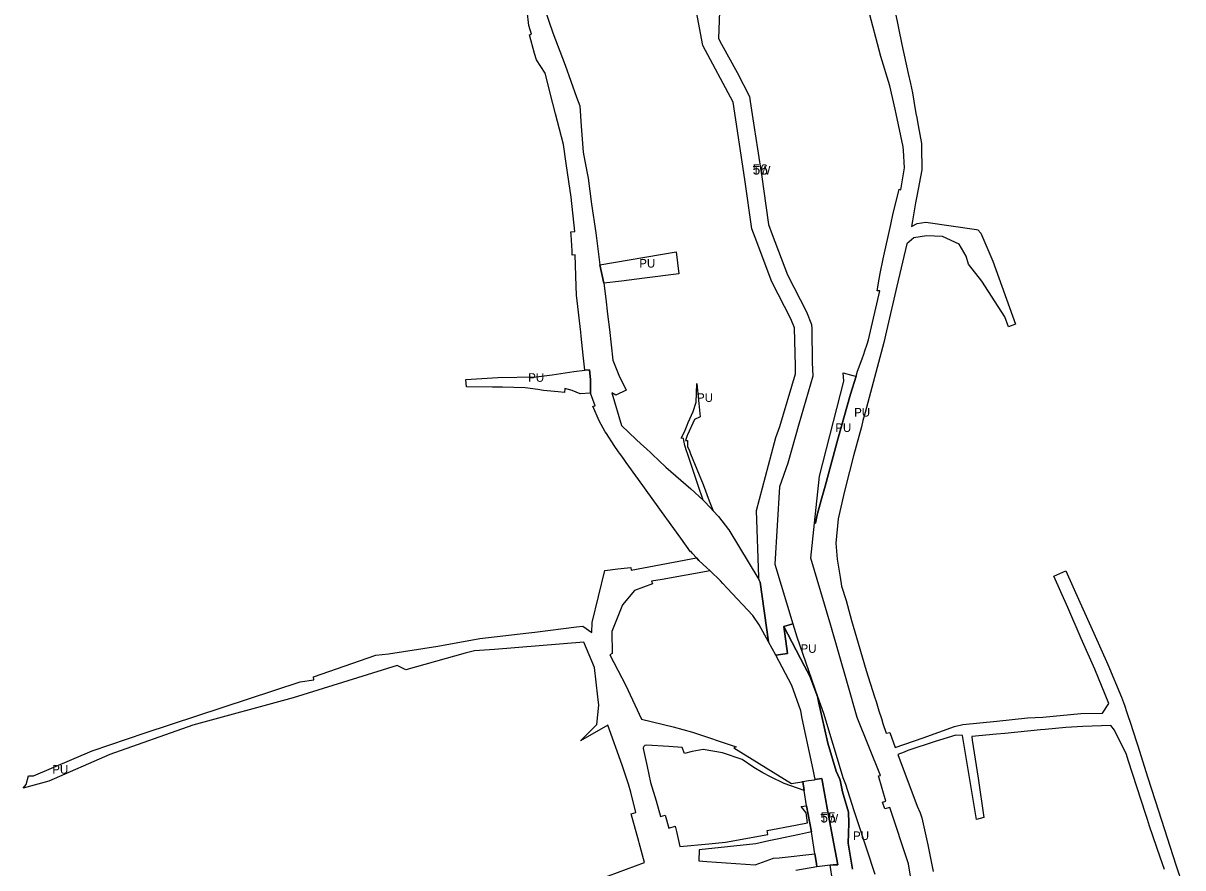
# Model space of a CAD drawing. Extents: x -519992 to -518210, y -1182334 to -1179965.
# Drawn here: x -519945 to -519268, y -1181126 to -1180633 of the extents above; entities that cross this region are included whole.
import ezdxf

# ---------------------------------------------------------------- set-up
doc = ezdxf.new("R2010")
doc.units = 0
for name, color, linetype in [('90320013', 7, 'Continuous'), ('90390023', 7, 'Continuous'), ('90450013', 7, 'Continuous'), ('ID_navrh', 7, 'Continuous')]:
    doc.layers.add(name, color=color, linetype=linetype)

msp = doc.modelspace()

# ---------------------------------------------------------------- linework, layer by layer
at = {"layer": '90320013'}
for points in [[(-519643.53, -1180616.69), (-519635.98, -1180638.42), (-519628.93, -1180657.31), (-519622.17, -1180676.01), (-519620.34, -1180681.18), (-519619.51, -1180692.9), (-519618.34, -1180708.21), (-519617.339, -1180713.385), (-519615.43, -1180723.26), (-519613.46, -1180738.61), (-519611.07, -1180755.2), (-519608.56, -1180773.96), (-519606.24, -1180784.7), (-519605.17, -1180793.83), (-519604.12, -1180802.77), (-519603.07, -1180811.71), (-519602.03, -1180820.65), (-519600.98, -1180829.58), (-519597.47, -1180838.41), (-519593.19, -1180847.07), (-519599.23, -1180850.14), (-519601.69, -1180848.72), (-519595.9, -1180867.83), (-519587.492, -1180875.913), (-519584.77, -1180878.53), (-519581.3, -1180881.31), (-519578.83, -1180883.71), (-519573.15, -1180889.16), (-519571.18, -1180891.06), (-519570.15, -1180892.05), (-519555.6, -1180904.77), (-519548.27, -1180911.45), (-519547.97, -1180911.76), (-519544.06, -1180915.85), (-519542.51, -1180917.547), (-519539.42, -1180920.93), (-519533.54, -1180928.52), (-519533.39, -1180928.78), (-519515.87, -1180957.65), (-519515.052, -1180959.197), (-519510.156, -1180994.086), (-519515.56, -1180984.16), (-519519.34, -1180978.65), (-519534.26, -1180962.71), (-519536.78, -1180960), (-519538.27, -1180958.4), (-519544.2, -1180952.62), (-519544.45, -1180952.39), (-519546.12, -1180950.9), (-519550.82, -1180946.67), (-519552.21, -1180945.13), (-519554.56, -1180942.48), (-519555.47, -1180941.2), (-519555.69, -1180941.61), (-519561.4, -1180933.64), (-519569.51, -1180922.35), (-519570.19, -1180921.41), (-519586.04, -1180899.33), (-519593.25, -1180889.36), (-519594.44, -1180887.7), (-519596.41, -1180884.93), (-519597.177, -1180883.853), (-519597.72, -1180883.09), (-519600.19, -1180879.52), (-519604.81, -1180872.5), (-519605.44, -1180871.41), (-519609.09, -1180865.11), (-519612.74, -1180856.43), (-519611.35, -1180856.24), (-519614.16, -1180848.84), (-519614.11, -1180843.98), (-519614.08, -1180840.87), (-519614.64, -1180835.3), (-519617.31, -1180835.53), (-519618.36, -1180826.61), (-519619.44, -1180815.52), (-519619.68, -1180813.23), (-519622.23, -1180791.6), (-519622.48, -1180786.38), (-519623, -1180768.19), (-519624.74, -1180768.22), (-519624.79, -1180767.35), (-519624.88, -1180765.8), (-519625.38, -1180756.54), (-519625.47, -1180754.63), (-519623.23, -1180754.54), (-519625.42, -1180734.42), (-519626.72, -1180725.27), (-519628.23, -1180714.745), (-519629.82, -1180703.66), (-519634.45, -1180685.74), (-519636.11, -1180679.72), (-519640.61, -1180662.03), (-519645.67, -1180654.18), (-519646.72, -1180650.66), (-519649.68, -1180639.62), (-519648.62, -1180639.19), (-519650.1, -1180634.22), (-519650.98, -1180625.68)], [(-519471.4, -1181142.42), (-519474.11, -1181124.5), (-519472.35, -1181124.27), (-519469.67, -1181124.26), (-519472.75, -1181107.84), (-519475.47, -1181093.25), (-519479.111, -1181073.792), (-519481.72, -1181074.28), (-519482.86, -1181074.48), (-519482.89, -1181074.28), (-519483.28, -1181072.51), (-519484.09, -1181068.69), (-519490.5, -1181038.91), (-519491.36, -1181034.38), (-519496.49, -1181019.52), (-519505.888, -1181001.924), (-519499.091, -1181000.97), (-519501.31, -1180985.158), (-519501.31, -1180985.158), (-519489.07, -1181008.29), (-519486, -1181014.08), (-519481.61, -1181026.09), (-519480.76, -1181029.97), (-519475.62, -1181053.25), (-519470.64, -1181069.59), (-519468.68, -1181073.93), (-519468.3, -1181074.78), (-519467.01, -1181081.67), (-519463.46, -1181093.59), (-519463.25, -1181100.05), (-519463.67, -1181111.66), (-519461.06, -1181126.84)]]:
    msp.add_lwpolyline(points, dxfattribs=at)
at = {"layer": '90390023'}
msp.add_lwpolyline([(-519538.72, -1180626.02), (-519539.34, -1180641.78), (-519537.56, -1180645.04), (-519528.51, -1180661.68), (-519521.28, -1180675.74), (-519520.86, -1180678.68), (-519518.61, -1180693.85), (-519516.57, -1180706.21), (-519514.02, -1180722.61), (-519511.64, -1180739.35), (-519510.24, -1180750.45), (-519508.12, -1180756.22), (-519499.04, -1180779.81), (-519488.01, -1180801.32), (-519485, -1180808.75), (-519484.955, -1180811.364), (-519484.62, -1180831.05), (-519484.35, -1180839.02), (-519492.45, -1180866.93), (-519498.93, -1180889.82), (-519503.72, -1180903.54), (-519506.51, -1180948.83), (-519495.882, -1180983.494), (-519495.882, -1180983.494), (-519501.31, -1180985.158), (-519499.091, -1181000.97), (-519505.888, -1181001.924), (-519505.89, -1181001.92), (-519510.156, -1180994.086), (-519515.052, -1180959.197), (-519515.87, -1180957.65), (-519515.91, -1180956.32), (-519517.16, -1180917.39), (-519506.67, -1180877.65), (-519505.87, -1180874.79), (-519503.51, -1180868.43), (-519494.382, -1180837.656), (-519494.477, -1180833.221), (-519494.958, -1180810.802), (-519497.111, -1180805.487), (-519508.188, -1180783.886), (-519518.042, -1180758.055), (-519519.994, -1180752.937), (-519523.917, -1180724.048), (-519530.903, -1180678.942), (-519548.528, -1180645.8), (-519554.552, -1180613.614)], dxfattribs=at)
msp.add_lwpolyline([(-519483.39, -1181074.57), (-519482.86, -1181074.48), (-519481.72, -1181074.28), (-519479.111, -1181073.792), (-519475.47, -1181093.25), (-519472.75, -1181107.84), (-519469.67, -1181124.26), (-519472.35, -1181124.27), (-519474.11, -1181124.5), (-519482.04, -1181125.48), (-519482.19, -1181123.5), (-519483.19, -1181117.77), (-519485.17, -1181105.08), (-519488.01, -1181089.82), (-519489.31, -1181080.9), (-519490.069, -1181075.691), (-519486.81, -1181075.14), (-519485, -1181074.84)], close=True, dxfattribs=at)
at = {"layer": '90450013'}
for points in [[(-519422.52, -1181160.74), (-519428.49, -1181123.78), (-519439.26, -1181090.75), (-519442.29, -1181091.61), (-519443.6, -1181087.68), (-519441.75, -1181087.15), (-519445.99, -1181072.34), (-519444.83, -1181072.14), (-519458.43, -1181038.3), (-519464.097, -1181018.489), (-519473.83, -1180984.46), (-519485.52, -1180945.19), (-519483.313, -1180924.749), (-519482.84, -1180924.79), (-519481.85, -1180919.92), (-519479.5, -1180911.27), (-519477.11, -1180903.14), (-519469.64, -1180875.84), (-519462.25, -1180849.48), (-519459.09, -1180839.02), (-519458.21, -1180836.1), (-519455.52, -1180828.94), (-519454.61, -1180826.08), (-519453.99, -1180824.16), (-519452.54, -1180820.3), (-519451.86, -1180817.69), (-519445.23, -1180789.12), (-519446.84, -1180789.14), (-519445.34, -1180781.17), (-519444.96, -1180779.04), (-519443.28, -1180770.51), (-519438.69, -1180750.32), (-519437.41, -1180743.8), (-519434.95, -1180733.91), (-519434, -1180729.75), (-519432.85, -1180730.12), (-519430.85, -1180717.29), (-519431.36, -1180707.27), (-519431.54, -1180705.01), (-519435.63, -1180685.7), (-519436.217, -1180683.095), (-519439.31, -1180669.37), (-519444.65, -1180652.26), (-519452.21, -1180623.57)], [(-519436.32, -1180626.33), (-519432.39, -1180645.23), (-519428.73, -1180662.21), (-519427.33, -1180668.08), (-519426.65, -1180670.89), (-519426.19, -1180673.47), (-519424.481, -1180683.286), (-519423.92, -1180686.51), (-519423.83, -1180687.01), (-519422.8, -1180692.56), (-519420.82, -1180703.19), (-519420.85, -1180704.99), (-519420.75, -1180718.5), (-519423.58, -1180733.94), (-519424.34, -1180737.85), (-519426.15, -1180748.26), (-519426.74, -1180751.52), (-519423.44, -1180749.75), (-519418.37, -1180749.12), (-519388.8, -1180753.34), (-519387.89, -1180753.47), (-519386.31, -1180755.46), (-519379.31, -1180771.85), (-519365.939, -1180808.674), (-519370.039, -1180810.159), (-519372.21, -1180804.27), (-519385.65, -1180783.52), (-519393.46, -1180773.55), (-519394.89, -1180768.85), (-519398.86, -1180761.99), (-519408.54, -1180757.43), (-519417.92, -1180757.11), (-519425.35, -1180758.21), (-519429.49, -1180761.65), (-519435.25, -1180786.33), (-519441.26, -1180812.55), (-519442.81, -1180819.34), (-519453.71, -1180860.16), (-519455.07, -1180864.93), (-519455.96, -1180868.52), (-519460.54, -1180885.48), (-519465.25, -1180903.71), (-519466.45, -1180908.71), (-519469.54, -1180922.26), (-519470.92, -1180936.46), (-519470.06, -1180945.82), (-519468.41, -1180956.34), (-519467.6, -1180961.57), (-519464.92, -1180969.89), (-519461.64, -1180981.59), (-519457.8, -1180994.9), (-519453.13, -1181010.79), (-519448.29, -1181026.1), (-519447.41, -1181028.9), (-519445.78, -1181034.36), (-519444.29, -1181038.85), (-519443.38, -1181041.69), (-519441.5, -1181047.44), (-519439.26, -1181047.02), (-519436.25, -1181055.74), (-519419.97, -1181050.04), (-519401.58, -1181043.58), (-519396.83, -1181042.33), (-519376.97, -1181040.328), (-519358.93, -1181038.51), (-519349.98, -1181038.06), (-519327.92, -1181035.88), (-519315.14, -1181035.78), (-519311.44, -1181030.17), (-519319.66, -1181010.12), (-519327.57, -1180992.13), (-519335.51, -1180974.07), (-519343.59, -1180955.68), (-519336.6, -1180952.66), (-519328.45, -1180970.85), (-519320.25, -1180989.03), (-519312.09, -1181007.32), (-519304.04, -1181026.3), (-519302.41, -1181031.03), (-519300.94, -1181035.39), (-519298.37, -1181043.36), (-519297.95, -1181044.61), (-519294.78, -1181054.26), (-519288.79, -1181073.49), (-519282.57, -1181092.81), (-519272.32, -1181124.33), (-519268.33, -1181136.35)], [(-519608.92, -1181132.65), (-519582.6, -1181122.9), (-519585.59, -1181111.4), (-519585.78, -1181110.65), (-519590.39, -1181094.44), (-519587.64, -1181093.79), (-519590.56, -1181081.86), (-519591.82, -1181077.19), (-519595.62, -1181066.11), (-519603.92, -1181042.71), (-519619.85, -1181051.79), (-519610.42, -1181042.39), (-519609.3, -1181031.01), (-519609.82, -1181026.13), (-519611.67, -1181008.98), (-519617.97, -1180994.34), (-519670.15, -1180998.58), (-519681.85, -1180999.38), (-519687.21, -1181000.66), (-519721.82, -1181010.41), (-519727.01, -1181007.89), (-519787.58, -1181026.69), (-519846.27, -1181042.69), (-519894.68, -1181059.82), (-519930.37, -1181075.45), (-519945.25, -1181079.6), (-519943.52, -1181077.33), (-519942.24, -1181072.32), (-519939.24, -1181072.38), (-519904.93, -1181057.82), (-519874, -1181047.31), (-519783.56, -1181017.44), (-519775.53, -1181016.2), (-519775.78, -1181014.56), (-519739.37, -1181001.84), (-519732.07, -1181001.04), (-519703.22, -1180996.55), (-519678.66, -1180992.11), (-519649.99, -1180988.87), (-519646.52, -1180988.48), (-519622.25, -1180985.42), (-519618.58, -1180984.97), (-519613.35, -1180988.59), (-519613.1, -1180982.71), (-519605.81, -1180952.5), (-519598.22, -1180951.43), (-519592.55, -1180950.85), (-519590.499, -1180950.64), (-519590.34, -1180952.29), (-519555.31, -1180945.69), (-519552.21, -1180945.13), (-519550.82, -1180946.67), (-519546.12, -1180950.9), (-519544.45, -1180952.39), (-519544.2, -1180952.62), (-519572.18, -1180957.71), (-519578.42, -1180958.74), (-519577.91, -1180960.17), (-519588.49, -1180964.17), (-519595.48, -1180972.43), (-519601.57, -1180988.02), (-519601.48, -1181000.85), (-519602.83, -1181001.58), (-519593.54, -1181019.57), (-519584.31, -1181039.15), (-519565.86, -1181043.66), (-519554.64, -1181046.86), (-519529.04, -1181055.4), (-519530.46, -1181056), (-519496.73, -1181076.82), (-519490.77, -1181075.81), (-519490.069, -1181075.691), (-519489.31, -1181080.9), (-519500.96, -1181076.8), (-519509, -1181072.88), (-519513.55, -1181070.5), (-519518.65, -1181067.52), (-519525.64, -1181062.82), (-519536.97, -1181058.86), (-519548.35, -1181056.85), (-519554.69, -1181058.15), (-519559.13, -1181059.28), (-519560.67, -1181055.79), (-519568.34, -1181055.22), (-519581.33, -1181054.34), (-519582.31, -1181054.66), (-519582.97, -1181055.28), (-519583.34, -1181056.03), (-519583.37, -1181056.44), (-519580.99, -1181066.96), (-519579.03, -1181076.12), (-519575.73, -1181086.85), (-519573.16, -1181096.07), (-519570.49, -1181095.25), (-519568.29, -1181102.8), (-519564.76, -1181101.75), (-519563.98, -1181104.86), (-519561.94, -1181113.51), (-519545.06, -1181111.98), (-519535.33, -1181111.09), (-519510.63, -1181106.57), (-519510.87, -1181104.32), (-519494.34, -1181101.03), (-519487.41, -1181099.84), (-519488.13, -1181093.94), (-519491.03, -1181090.25), (-519488.01, -1181089.82), (-519485.17, -1181105.08), (-519492.17, -1181106.48), (-519505.15, -1181109.31), (-519509.92, -1181110.35), (-519517.54, -1181112), (-519550.68, -1181115.46), (-519550.86, -1181121.89), (-519546.1, -1181122.28), (-519517.89, -1181124.37), (-519507.26, -1181120.39), (-519503.93, -1181120.12), (-519483.19, -1181117.77), (-519482.19, -1181123.5), (-519482.04, -1181125.48), (-519494.21, -1181127.6)], [(-519461.06, -1181126.84), (-519463.67, -1181111.66), (-519463.25, -1181100.05), (-519463.46, -1181093.59), (-519467.01, -1181081.67), (-519468.3, -1181074.78), (-519468.68, -1181073.93), (-519470.64, -1181069.59), (-519475.62, -1181053.25), (-519480.76, -1181029.97), (-519481.61, -1181026.09), (-519478.17, -1181035.82), (-519467.25, -1181071.87), (-519466.73, -1181073.28), (-519465.27, -1181077.26), (-519460.28, -1181092.58), (-519458.37, -1181098.48), (-519448.2, -1181129.83)], [(-519279.05, -1181127), (-519281.47, -1181119.77), (-519287.7, -1181101.63), (-519289.01, -1181097.84), (-519289.89, -1181094.91), (-519300.24, -1181063.14), (-519301.18, -1181059.96), (-519308.3, -1181045.71), (-519310.44, -1181042.95), (-519326.68, -1181043.54), (-519336.68, -1181044.18), (-519348.66, -1181045.33), (-519351.47, -1181045.52), (-519372.259, -1181047.53), (-519377.12, -1181048), (-519391.57, -1181049.4), (-519391.25, -1181051.56), (-519387.88, -1181073.76), (-519384.4, -1181096.68), (-519388.73, -1181097.86), (-519396.31, -1181052.34), (-519396.89, -1181048.84), (-519400.74, -1181048.48), (-519412.82, -1181052.34), (-519428.78, -1181057.6), (-519430.97, -1181058.44), (-519434.66, -1181059.8), (-519423.47, -1181090.01), (-519421.71, -1181093.94), (-519420.7, -1181096.88), (-519417.22, -1181112.52), (-519414.06, -1181128.16)]]:
    msp.add_lwpolyline(points, dxfattribs=at)
for points in [[(-519606.24, -1180784.7), (-519608.56, -1180773.96), (-519564.086, -1180766.423), (-519562.58, -1180779.29), (-519582.53, -1180781.72), (-519595.95, -1180783.48)], [(-519617.31, -1180835.53), (-519614.64, -1180835.3), (-519614.08, -1180840.87), (-519614.11, -1180843.98), (-519614.16, -1180848.84), (-519620.14, -1180849.19), (-519624.81, -1180847.25), (-519629.07, -1180846.26), (-519629.32, -1180848.49), (-519632.91, -1180848.16), (-519641.5, -1180847.33), (-519644.78, -1180846.82), (-519652.15, -1180845.7), (-519665.48, -1180845.42), (-519671.23, -1180845.33), (-519686.446, -1180845.217), (-519686.95, -1180840.95), (-519668.26, -1180839.78), (-519645.73, -1180839.36), (-519636.43, -1180838.1), (-519623.77, -1180836.27)], [(-519482.84, -1180924.79), (-519483.313, -1180924.749), (-519480.35, -1180897.31), (-519466.18, -1180841.84), (-519466.67, -1180837.06), (-519461.01, -1180838.52), (-519459.09, -1180839.02), (-519462.25, -1180849.48), (-519469.64, -1180875.84), (-519477.11, -1180903.14), (-519479.5, -1180911.27), (-519481.85, -1180919.92)], [(-519542.51, -1180917.547), (-519544.06, -1180915.85), (-519547.97, -1180911.76), (-519548.27, -1180911.45), (-519551.19, -1180902.81), (-519557.48, -1180884.13), (-519557.98, -1180882.65), (-519558.85, -1180880.07), (-519559.05, -1180879.48), (-519559.61, -1180876.48), (-519559.8, -1180875.45), (-519561.21, -1180875.08), (-519559.21, -1180871.55), (-519557.68, -1180867.65), (-519557, -1180865.95), (-519554.1, -1180859.66), (-519552.33, -1180854.19), (-519552.3, -1180848.8), (-519551.97, -1180843.31), (-519550.05, -1180862.74), (-519553.47, -1180864.26), (-519557.41, -1180873.23), (-519557.57, -1180873.54), (-519558.7, -1180876.44), (-519557.41, -1180876.44), (-519557.41, -1180879.99), (-519556.347, -1180882.568), (-519555.638, -1180884.289), (-519548.26, -1180902.19), (-519544.83, -1180911.8), (-519542.86, -1180916.68)], [(-519501.31, -1180985.158), (-519501.31, -1180985.158), (-519495.882, -1180983.494), (-519495.882, -1180983.494), (-519493.55, -1180991.1), (-519481.61, -1181026.09), (-519486, -1181014.08), (-519489.07, -1181008.29)]]:
    msp.add_lwpolyline(points, close=True, dxfattribs=at)

# ---------------------------------------------------------------- texts
at = {"layer": '90390023'}
for rotation, p in [(0, (-519519.451, -1180721.2702)), (360, (-519479.8695, -1181099.5728))]:
    msp.add_text('TW', height=5, rotation=rotation, dxfattribs=at).set_placement(p)
at = {"layer": '90450013'}
for rotation, p in [(0.0000001, (-519585.6152, -1180775.5615)), (360, (-519650.4452, -1180842.245)), (360, (-519551.86, -1180853.9838)), (360, (-519460.1528, -1180862.55)), (360, (-519471.2015, -1180871.5219)), (360, (-519491.46, -1181000.499)), (360, (-519928.2713, -1181071.0745)), (360, (-519460.77, -1181109.7989))]:
    msp.add_text('PU', height=5, rotation=rotation, dxfattribs=at).set_placement(p)
at = {"layer": 'ID_navrh'}
for s, rotation, p in [('56', 0, (-519519.451, -1180721.2702)), ('55', 360, (-519479.8695, -1181099.5728))]:
    msp.add_text(s, height=6, rotation=rotation, dxfattribs=at).set_placement(p)

doc.saveas('drawing.dxf')
